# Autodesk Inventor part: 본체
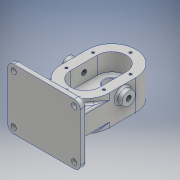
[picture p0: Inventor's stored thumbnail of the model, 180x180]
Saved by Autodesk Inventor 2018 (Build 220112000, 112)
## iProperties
Created: 2020-09
Part Number: 본체
Material: 알루미늄 6061
Document SubType Name: Modeling
Designer: Administrator
Density: 2.7 g/cm^3
Appearance: 알루미늄 - 평지
Mass: 1440.46 g
Surface Area: 785.636 cm^2
Volume: 533.505 cm^3
Author: Administrator
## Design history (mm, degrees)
sketch "스케치1"
  geometry: L1 (-40, 0)-(-40, -44); L2 (40, 0)-(40, -44); A1 r 40 centre (0, 0) between (40, 0) and (-40, 0); A2 r 40 centre (0, -44) between (-40, -44) and (40, -44)
  constraints: 4 end point, 4 point on circle, 2 centre point, 2 tangent, 1 parallel, 1 vertical
  dimensions: "d2" = 80 diameter of A1; "d4" = 80 diameter of A2; "d5" = 40 distance from line of A2.centre L1; "d6" = 59.46427 distance of L2.start A2.centre
extrude "돌출1" new body sketch "스케치1" stored distance "d7" = 53; taper "d8" = 0 deg
node "작업 평면1"
sketch "스케치2"
  geometry: L1 (-40, -44)-(-40, -107); L2 (-40, -107)-(40, -107); L3 (40, -44)-(40, 0) reference; L4 (40, -107)-(40, -44); L5 (40, -44)-(-40, -44); A1 r 40 centre (0, -44) between (-40, -44) and (40, -44) reference; 1 further point
  constraints: 8 end point, 2 perpendicular, 1 collinear, 1 tangent
  dimensions: "d14" = 63 distance between parallel lines of L5 L2
extrude "돌출2" join sketch "스케치2" stored distance "d15" = 37; taper "d16" = 0 deg
sketch "스케치3"
  geometry: L1 (-112, -43.5)-(-102, -43.5); L2 (-102, -43.5)-(-102, 56.5); L3 (-102, 56.5)-(-112, 56.5); L4 (-112, 56.5)-(-112, -43.5); 2 further points
  constraints: 8 end point, 2 vertical, 1 horizontal, 1 parallel
  dimensions: "d21" = 10 distance between parallel lines of L2 L4; "d22" = 100 distance between parallel lines of L3 L1; "d23" = 102 distance from line of point (0, 0) L2; "d24" = 56.5 distance from line of point (0, 0) L3
extrude "돌출3" join sketch "스케치3" stored distance "d25" = 120; taper "d26" = 0 deg
sketch "스케치4"
  geometry: L1 (-24, 0)-(-24, -44); L2 (24, 0)-(24, -44); A1 r 24 centre (0, 0) between (24, 0) and (-24, 0); A2 r 24 centre (0, -44) between (-24, -44) and (24, -44); 1 further point
  constraints: 4 end point, 4 point on circle, 4 tangent, 2 centre point, 2 vertical, 1 coincident
  dimensions: "d30" = 24 radius of A1; "d31" = 50.11986 distance of L2.end point (0, 0)
extrude "돌출4" cut sketch "스케치4" distance "d32" = 29; taper "d33" = 0 deg
sketch "스케치5"
  geometry: C1 r 12.5 at (0, 0); C2 r 12.5 at (0, -44)
  constraints: 2 centre point, 1 equal radius
extrude "돌출5" cut sketch "스케치5" distance "d39" = 15; taper "d40" = 0 deg
sketch "스케치6"
  geometry: C1 r 19 at (0, 0); 1 further point
  constraints: 1 centre point, 1 coincident
  dimensions: "d41" = 38 diameter of C1
extrude "돌출6" join sketch "스케치6" distance "d42" = 17; taper "d43" = 0 deg
hole "구멍1" diameter "d53" = 17; stored, may be unused: countersink angle "d57" = 90 deg, drill point angle "d59" = 118 deg; dims "d51" = 10, "d52" = 10, "d54" = 6, "d55" = 28, "d56" = 7.3, "d58" = 8
sketch "스케치8"
  geometry: C1 r 2.5 at (0, 31); C2 r 2.5 at (0, -75); C3 r 2.5 at (-31, -44); C4 r 2.5 at (31, -44); C5 r 2.5 at (31, 0); C6 r 2.5 at (-31, 0); 2 further points
  constraints: 6 centre point
  dimensions: "d62" = 5 diameter of C1; "d63" = 5 diameter of C2; "d64" = 5 diameter of C3; "d65" = 5 diameter of C4; "d66" = 5 diameter of C5; "d67" = 5 diameter of C6; "d68" = 31 distance of point (0, 0) C5.centre; "d69" = 53.82379 distance of point (0, -44) C5.centre; "d70" = 53.82379 distance of point (0, 0) C4.centre; "d71" = 31 distance of point (0, -44) C4.centre; "d72" = 31 distance of point (0, 0) C1.centre; "d73" = 75 distance of point (0, -44) C1.centre; "d74" = 75 distance of point (0, 0) C2.centre; "d75" = 31 distance of point (0, 0) C6.centre; "d76" = 53.82379 distance of point (0, 0) C3.centre; "d77" = 31 distance of point (0, -44) C2.centre; "d78" = 53.82379 distance of point (0, -44) C6.centre; "d79" = 31 distance of point (0, -44) C3.centre
hole "구멍2" sketch "스케치8" at (0, 31), (31, 0), (-31, 0), (-31, -44), (31, -44), (0, -75) diameter "d80" = 4.134; stored, may be unused: countersink angle "d84" = 90 deg, drill point angle "d86" = 118 deg; dims "d81" = 10, "d82" = 28, "d83" = 7.3, "d85" = 12
sketch "스케치9"
  geometry: L1 (0, -43.5)-(14.404, -43.5); L2 (14, -42.8)-(0, -42.8); L3 (0, -42.8)-(0, -43.5); L4 (14, -42.8)-(14.404, -43.5); 1 further point
  constraints: 8 end point, 1 horizontal, 1 parallel, 1 vertical
  dimensions: "d89" = 120 deg angle of L2 L4; "d90" = 0.7 distance between parallel lines of L2 L1; "d91" = 9.27564 distance from line of point (0, 0) L4; "d92" = 42.8 distance from line of point (0, 0) L2; "d93" = 0 distance from line of point (0, 0) L3
revolve "회전1" sketch "스케치9" stored, may be unused: angle "d94" = 90 deg
sketch "스케치10"
  geometry: L1 (0, 44)-(0, 0) reference; L2 (0, 22)-(-14, 22); C1 r 11 at (-14, 22); 1 further point
  constraints: 2 end point, 1 centre point, 1 coincident, 1 horizontal, 1 midpoint
  dimensions: "d95" = 14 distance of L2.start L2.end; "d96" = 22 diameter of C1
extrude "돌출7" join sketch "스케치10" distance "d97" = 10; taper "d98" = 0 deg
hole "구멍3" diameter "d102" = 8.376; stored, may be unused: countersink angle "d106" = 90 deg, drill point angle "d108" = 118 deg; dims "d103" = 20, "d104" = 28, "d105" = 7.3, "d107" = 27.3, "d128" = 10, "d129" = 10
node "작업 평면2"
sketch "스케치12"
  geometry: L1 (0, 0)-(120, 0) reference; L2 (0, 0)-(0, 100) reference; 2 further points
  constraints: 1 other
  dimensions: "d112" = 12 distance from line of L1 point (60, 12); "d113" = 60 distance from line of L2 point (60, 12)
feature "엠보싱1" sketch "스케치12" dims "d2" = 80, "d4" = 80, "d5" = 40, "d6" = 59.46427, "d114" = 0.5, "d115" = 0
fillet "모깎기1" dims "d116" = 10
fillet "모깎기2" dims "d117" = 3
fillet "모깎기3" dims "d118" = 0.5
chamfer "모따기1" distance "d119" = 1; stored, may be unused: second distance "d120" = 2, angle "d121" = 45 deg
sketch "스케치13"
  geometry: C1 r 4.5 at (0, -7); C2 r 4.5 at (100, -7); C3 r 4.5 at (0, -87); C4 r 4.5 at (100, -87); A1 r 7 centre (0, -7) between (0, 0) and (-7, -7) reference; A2 r 7 centre (100, -7) between (107, -7) and (100, 0) reference; A3 r 7 centre (0, -87) between (-7, -87) and (0, -94) reference; A4 r 7 centre (100, -87) between (100, -94) and (107, -87) reference; 1 further point
  constraints: 4 centre point, 4 coincident
  dimensions: "d122" = 9 diameter of C1; "d123" = 9 diameter of C2; "d124" = 9 diameter of C3; "d125" = 9 diameter of C4
extrude "돌출8" cut sketch "스케치13" distance "d126" = 50; taper "d127" = 0 deg
node "솔리드1"
mirror "미러1"
